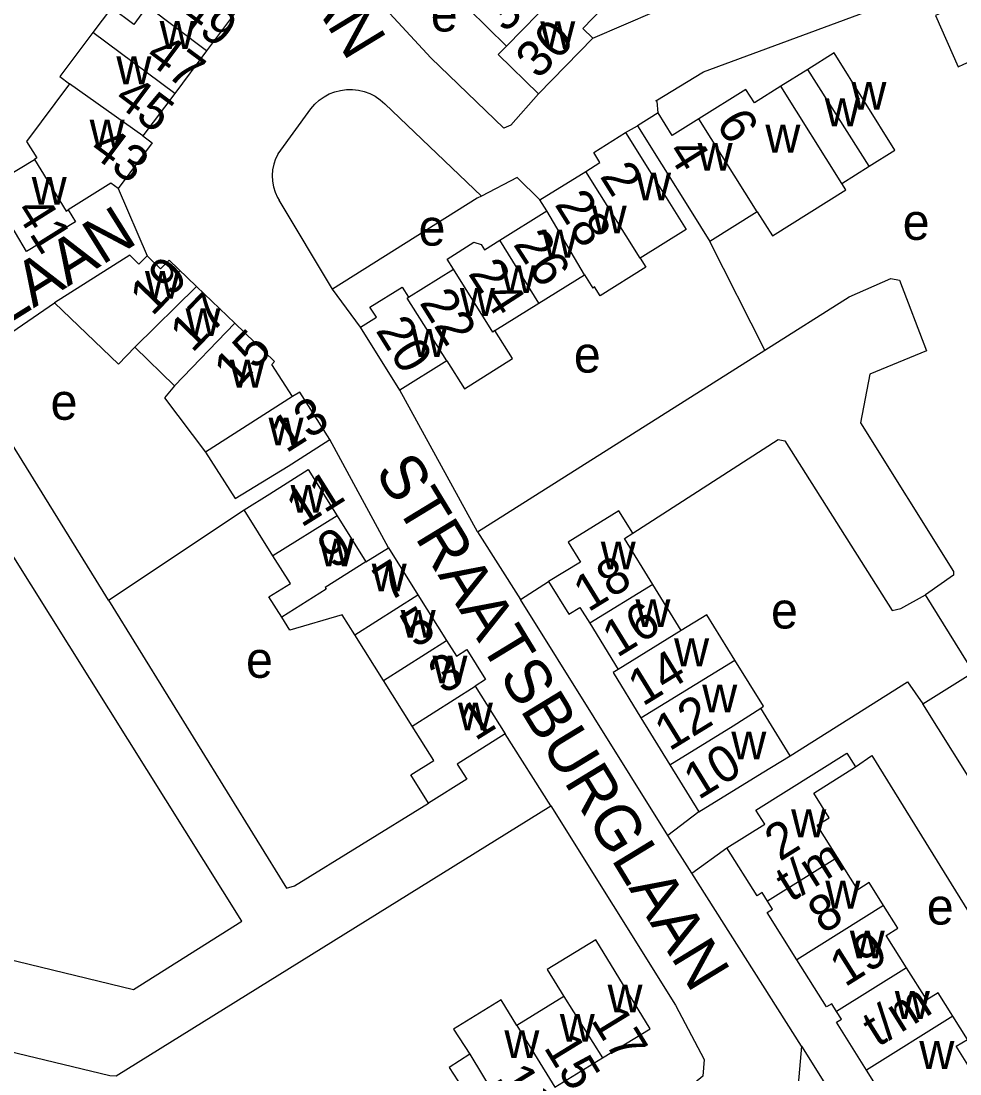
# Model space of a CAD drawing. Extents: x 157768 to 159790, y 387230 to 389604.
# Drawn here: x 158696.4 to 158800.1, y 388182.9 to 388299.1 of the extents above; entities that cross this region are included whole.
import ezdxf

# ---------------------------------------------------------------- set-up
doc = ezdxf.new("R2010")
doc.units = 0
for name, color, linetype in [('BLT_Basislijn', 7, 'Continuous'), ('BLT_Bebouwing', 7, 'Continuous'), ('BLT_Centroide', 7, 'Continuous'), ('BLT_Huisnummer', 7, 'Continuous'), ('BLT_Huisnummer_ tussenligend', 7, 'Continuous'), ('BLT_Huisnummer_reeks', 7, 'Continuous'), ('BLT_Onderverdeling_panden', 7, 'Continuous'), ('BLT_Straatnaam', 7, 'Continuous')]:
    doc.layers.add(name, color=color, linetype=linetype)

msp = doc.modelspace()

# ---------------------------------------------------------------- linework, layer by layer
at = {"layer": 'BLT_Basislijn'}
for p, q in [((158759.54, 388297.26), (158769.82, 388301.71)), ((158724.78, 388284.49), (158728.4, 388289.46)), ((158736.58, 388289.99), (158747.25, 388279.82)), ((158763.16, 388286.83), (158764.46, 388287.58)), ((158707.13, 388280.65), (158710.32, 388273.23)), ((158730.79, 388269.53), (158724.9, 388279.35)), ((158746.78, 388279.58), (158730.79, 388269.53)), ((158747.25, 388279.82), (158746.78, 388279.58)), ((158778.52, 388262.81), (158772.45, 388274.78)), ((158733.87, 388265.33), (158730.79, 388269.53)), ((158746.79, 388242.74), (158778.52, 388262.81)), ((158746.79, 388242.74), (158738.23, 388258.37)), ((158736.96, 388240.97), (158730.51, 388252.94)), ((158706.07, 388235.18), (158721.03, 388245.16)), ((158746.79, 388242.74), (158751.54, 388235.25)), ((158751.54, 388235.25), (158754.66, 388237.24)), ((158767.82, 388209.21), (158751.54, 388235.25)), ((158801.57, 388227.22), (158796.28, 388235.78)), ((158754.91, 388212.48), (158749.86, 388220.41)), ((158771.24, 388211.81), (158767.82, 388209.21)), ((158770.46, 388205.05), (158767.82, 388209.21)), ((158770.46, 388205.05), (158774.34, 388207.84)), ((158782.57, 388185.91), (158770.46, 388205.05)), ((158782.57, 388185.91), (158794.71, 388166.77))]:
    msp.add_line(p, q, dxfattribs=at)
for points in [[(158753.53, 388291.11), (158750.47, 388287.65), (158749.71, 388287.32), (158741.65, 388295.09), (158737.13, 388299.97), (158739.46, 388302.38)], [(158766.75, 388289.01), (158766.65, 388290.26), (158766.48, 388290.33), (158771.75, 388293.55), (158796.8, 388302.82)], [(158728.4, 388289.46), (158728.84, 388289.96), (158729.32, 388290.4), (158729.86, 388290.78), (158730.44, 388291.09), (158731.05, 388291.33), (158731.69, 388291.49), (158732.35, 388291.58), (158733, 388291.59), (158733.66, 388291.51), (158734.3, 388291.36), (158734.92, 388291.13), (158735.5, 388290.83), (158736.05, 388290.46), (158736.58, 388289.99)], [(158724.78, 388284.49), (158724.51, 388283.93), (158724.3, 388283.33), (158724.17, 388282.71), (158724.12, 388282.08), (158724.15, 388281.45), (158724.26, 388280.83), (158724.45, 388280.23), (158724.71, 388279.66), (158724.9, 388279.35)], [(158753.7, 388279.4), (158751.18, 388281.86), (158747.25, 388279.82)], [(158778.52, 388262.81), (158787.84, 388268.69), (158792.44, 388270.72), (158793.4, 388270.53), (158796.38, 388262.74), (158790.14, 388260.15), (158789.09, 388254.78), (158799.37, 388238.34), (158799.37, 388237.95), (158796.28, 388235.78)], [(158706.07, 388235.18), (158705.48, 388236.13), (158693.99, 388254.66), (158690.52, 388260.86), (158690.65, 388261.55), (158700.1, 388268.01)], [(158666.08, 388241.43), (158650.47, 388231.51), (158669.07, 388201.82), (158708.81, 388192.17), (158720.79, 388199.72), (158684.89, 388256.97)], [(158763.95, 388242.59), (158779.99, 388252.92), (158780.72, 388252.8), (158792.6, 388234.05), (158793.55, 388234.28), (158796.28, 388235.78)], [(158706.07, 388235.18), (158725.7, 388203.39), (158726.59, 388203.62), (158741.41, 388212.75)], [(158781.31, 388218.01), (158794.29, 388226.18), (158795.99, 388223.74)], [(158754.91, 388212.48), (158768.65, 388190.46), (158771.84, 388184.46), (158771.68, 388182.61), (158768.32, 388179.87), (158719.99, 388149.59), (158716.6, 388147.54), (158715.16, 388147.58), (158654.55, 388162.64), (158646.18, 388166.5), (158640.59, 388170.73), (158635.71, 388176.23), (158633.8, 388179.81), (158621.93, 388198.67), (158609.83, 388218.76), (158609.61, 388219.13)], [(158788.54, 388216.76), (158790.35, 388218.02), (158814.79, 388178.48)], [(158664.28, 388192.84), (158665.72, 388193.71), (158692.01, 388187.29), (158692.87, 388185.9), (158706.22, 388182.68), (158706.92, 388182.64), (158754.91, 388212.48)], [(158782.57, 388185.91), (158781.74, 388176.16), (158788.72, 388165.04), (158789.73, 388164.14), (158790.36, 388164.14), (158794.71, 388166.77)]]:
    msp.add_lwpolyline(points, dxfattribs=at)
at = {"layer": 'BLT_Bebouwing'}
for p, q in [((158720.41, 388300.58), (158716.89, 388295.87)), ((158749.99, 388296.38), (158745.8, 388300.48)), ((158759.54, 388297.26), (158753.53, 388291.11)), ((158716.89, 388295.87), (158713.37, 388291.16)), ((158713.37, 388291.16), (158709.85, 388286.45)), ((158766.75, 388289.01), (158764.46, 388287.58)), ((158753.7, 388279.4), (158758.78, 388282.54)), ((158787.02, 388281.22), (158790.05, 388283.11)), ((158754.45, 388278.19), (158753.7, 388279.4)), ((158749.28, 388274.95), (158754.45, 388278.19)), ((158777.7, 388278.07), (158772.45, 388274.78)), ((158739.18, 388268.64), (158744.15, 388271.74)), ((158738.23, 388258.37), (158733.87, 388265.33)), ((158708.97, 388263.11), (158713.33, 388258.87)), ((158743.41, 388261.61), (158738.23, 388258.37)), ((158724.22, 388240.07), (158721.03, 388245.16)), ((158731.29, 388244.5), (158734.49, 388239.41)), ((158734.49, 388239.41), (158736.96, 388240.97)), ((158736.96, 388240.97), (158740.22, 388235.78)), ((158740.22, 388235.78), (158743.38, 388230.74)), ((158759.19, 388232.63), (158762.33, 388227.54)), ((158736.43, 388226.31), (158733.27, 388231.35)), ((158795.99, 388223.74), (158801.57, 388227.22)), ((158739.6, 388221.27), (158736.43, 388226.31)), ((158746.55, 388225.7), (158749.86, 388220.41)), ((158803.98, 388210.94), (158795.99, 388223.74)), ((158764.85, 388222.19), (158768.05, 388217)), ((158768.05, 388217), (158771.24, 388211.81)), ((158771.24, 388211.81), (158778.25, 388216.12)), ((158756.34, 388191.4), (158751.16, 388188.22)), ((158755.35, 388181.4), (158760.62, 388184.63))]:
    msp.add_line(p, q, dxfattribs=at)
for points in [[(158759.54, 388297.26), (158758.44, 388298.34), (158760.64, 388300.59), (158757.43, 388303.74), (158755.88, 388302.16), (158755.77, 388302.27)], [(158796.8, 388302.82), (158798.02, 388300.06), (158797.38, 388299.77), (158799.88, 388294.1), (158800.52, 388294.39), (158801.87, 388294.98), (158801.96, 388294.75)], [(158710.34, 388300.77), (158708.85, 388298.78), (158706.39, 388300.62), (158704.34, 388297.87)], [(158704.34, 388297.87), (158700.7, 388293.01), (158701.75, 388292.22)], [(158753.53, 388291.11), (158749.09, 388295.45), (158749.99, 388296.38)], [(158790.05, 388283.11), (158792.9, 388284.9), (158786.19, 388295.62), (158783.29, 388293.81)], [(158783.29, 388293.81), (158780.3, 388291.94)], [(158701.75, 388292.22), (158696.99, 388285.85), (158698.15, 388284.02), (158697.9, 388283.87)], [(158780.3, 388291.94), (158777.38, 388290.11)], [(158777.38, 388290.11), (158776.45, 388291.6), (158771.26, 388288.36)], [(158771.26, 388288.36), (158768.31, 388286.51), (158766.75, 388289.01)], [(158764.46, 388287.58), (158767.12, 388283.34), (158770.4, 388278.1), (158772.45, 388274.78)], [(158709.85, 388286.45), (158710.89, 388285.68), (158707.13, 388280.65)], [(158758.78, 388282.54), (158760.32, 388283.51), (158759.63, 388284.62), (158763.16, 388286.83)], [(158763.16, 388286.83), (158765.81, 388282.59), (158769.86, 388276.13), (158764.78, 388272.96)], [(158695.78, 388275.75), (158694.43, 388277.98), (158692.75, 388280.75), (158697.9, 388283.87)], [(158707.13, 388280.65), (158706.32, 388281.25), (158701.61, 388278.29)], [(158777.7, 388278.07), (158779.36, 388275.42), (158787.47, 388280.49), (158787.02, 388281.22)], [(158701.61, 388278.29), (158702.41, 388276.97), (158697.02, 388273.7), (158695.78, 388275.75)], [(158744.15, 388271.74), (158743.45, 388272.86), (158746.41, 388274.72), (158747.19, 388274.48), (158747.58, 388273.89), (158749.28, 388274.95)], [(158710.32, 388273.23), (158709.42, 388272.29), (158708.43, 388273.29), (158700.1, 388268.01)], [(158715.77, 388269.83), (158712.76, 388272.75), (158711.81, 388271.78), (158710.32, 388273.23)], [(158764.78, 388272.96), (158765.4, 388271.97), (158760.34, 388268.8), (158759.72, 388269.79), (158759.52, 388269.66)], [(158753.59, 388267.98), (158758.6, 388271.12)], [(158758.6, 388271.12), (158759.52, 388269.66)], [(158715.77, 388269.83), (158720.02, 388265.76)], [(158733.87, 388265.33), (158735.64, 388266.43), (158734.93, 388267.56), (158738.47, 388269.77), (158739.18, 388268.64)], [(158700.1, 388268.01), (158707.16, 388261.24), (158708.97, 388263.11)], [(158748.73, 388264.95), (158753.59, 388267.98)], [(158726.37, 388257.67), (158724.08, 388261.22), (158724.4, 388261.54), (158720.02, 388265.76)], [(158743.41, 388261.61), (158745.35, 388258.52), (158750.68, 388261.86), (158748.73, 388264.95)], [(158713.33, 388258.87), (158712.25, 388257.54), (158716.77, 388251.53)], [(158730.51, 388252.94), (158727.17, 388258.17), (158726.37, 388257.67)], [(158716.77, 388251.53), (158720.04, 388246.41), (158725.88, 388250), (158726.29, 388250.26), (158730.51, 388252.94)], [(158721.03, 388245.16), (158723.87, 388246.94), (158728.1, 388249.6), (158731.29, 388244.5)], [(158763.95, 388242.59), (158762.42, 388245.06), (158756.8, 388241.6), (158758.16, 388239.39), (158754.66, 388237.24)], [(158766.15, 388236.92), (158763.02, 388242.01), (158763.95, 388242.59)], [(158725.19, 388233.3), (158723.78, 388235.55), (158726.14, 388237.02), (158724.22, 388240.07)], [(158754.66, 388237.24), (158756.88, 388233.64), (158758.11, 388234.39), (158759.19, 388232.63)], [(158769.29, 388231.83), (158766.15, 388236.92)], [(158733.27, 388231.35), (158731.87, 388233.57), (158726.09, 388231.86), (158725.19, 388233.3)], [(158775.23, 388228.56), (158772.14, 388233.58), (158769.29, 388231.83)], [(158743.38, 388230.74), (158744.47, 388229), (158745.62, 388229.73), (158747.7, 388226.42), (158746.55, 388225.7)], [(158778.07, 388223.27), (158778.38, 388223.46), (158775.23, 388228.56)], [(158762.33, 388227.54), (158761.77, 388227.2), (158764.85, 388222.19)], [(158781.31, 388218.01), (158778.07, 388223.27)], [(158741.41, 388212.75), (158739.43, 388215.91), (158741.97, 388217.49), (158739.6, 388221.27)], [(158749.86, 388220.41), (158744.56, 388217.09), (158745.63, 388215.4), (158741.41, 388212.75)], [(158774.34, 388207.84), (158778.52, 388210.46), (158777.55, 388212.01), (158787.59, 388218.28), (158788.54, 388216.76)], [(158778.25, 388216.12), (158781.31, 388218.01)], [(158786.56, 388206.78), (158784.32, 388210.35), (158785.62, 388211.16), (158783.93, 388213.88), (158788.54, 388216.76)], [(158778.84, 388201.93), (158778.24, 388202.89), (158777.67, 388202.53), (158774.34, 388207.84)], [(158791.64, 388201.47), (158790.06, 388203.99), (158788.8, 388203.21), (158786.56, 388206.78)], [(158782.06, 388195.47), (158778.79, 388200.68), (158779.39, 388201.06), (158778.84, 388201.93)], [(158794.17, 388194.59), (158791.94, 388198.15), (158793.22, 388198.95), (158791.64, 388201.47)], [(158760.62, 388184.63), (158765.88, 388187.86), (158759.87, 388197.66), (158754.51, 388194.38), (158756.34, 388191.4)], [(158786.46, 388189.76), (158785.92, 388190.62), (158785.33, 388190.26), (158782.06, 388195.47)], [(158799.28, 388189.25), (158797.67, 388191.82), (158796.4, 388191.03), (158794.17, 388194.59)], [(158751.16, 388188.22), (158749.43, 388191.04), (158744.17, 388187.8), (158745.96, 388185.03)], [(158789.75, 388183.28), (158786.44, 388188.56), (158786.99, 388188.9), (158786.46, 388189.76)], [(158801.87, 388182.41), (158799.67, 388185.91), (158800.89, 388186.68), (158799.28, 388189.25)], [(158745.96, 388185.03), (158743.68, 388183.56), (158745.1, 388181.37), (158742.12, 388179.52)], [(158794.15, 388177.57), (158793.55, 388178.52), (158792.96, 388178.16), (158789.75, 388183.28)]]:
    msp.add_lwpolyline(points, dxfattribs=at)
at = {"layer": 'BLT_Onderverdeling_panden'}
for p, q in [((158749.99, 388296.38), (158755.77, 388302.27)), ((158716.89, 388295.87), (158710.34, 388300.77)), ((158713.37, 388291.16), (158704.34, 388297.87)), ((158790.05, 388283.11), (158783.29, 388293.81)), ((158709.85, 388286.45), (158701.75, 388292.22)), ((158787.02, 388281.22), (158780.3, 388291.94)), ((158777.7, 388278.07), (158771.26, 388288.36)), ((158764.78, 388272.96), (158758.78, 388282.54)), ((158758.6, 388271.12), (158754.45, 388278.19)), ((158753.59, 388267.98), (158749.28, 388274.95)), ((158715.77, 388269.83), (158708.97, 388263.11)), ((158726.37, 388257.67), (158716.77, 388251.53)), ((158731.29, 388244.5), (158724.22, 388240.07)), ((158766.15, 388236.92), (158759.19, 388232.63)), ((158733.27, 388231.35), (158740.22, 388235.78)), ((158769.29, 388231.83), (158762.33, 388227.54)), ((158736.43, 388226.31), (158743.38, 388230.74)), ((158764.85, 388222.19), (158775.23, 388228.56)), ((158739.6, 388221.27), (158746.55, 388225.7)), ((158775.05, 388221.31), (158778.07, 388223.27)), ((158768.05, 388217), (158775.05, 388221.31)), ((158786.56, 388206.78), (158778.84, 388201.93)), ((158791.64, 388201.47), (158782.06, 388195.47)), ((158794.17, 388194.59), (158786.46, 388189.76)), ((158756.34, 388191.4), (158760.62, 388184.63)), ((158799.28, 388189.25), (158789.75, 388183.28)), ((158751.16, 388188.22), (158755.35, 388181.4)), ((158745.96, 388185.03), (158751.96, 388175.17))]:
    msp.add_line(p, q, dxfattribs=at)
for points in [[(158697.9, 388283.87), (158701.37, 388278.14), (158701.61, 388278.29)], [(158748.73, 388264.95), (158748.5, 388264.8), (158744.15, 388271.74)], [(158743.41, 388261.61), (158739.04, 388268.55), (158739.18, 388268.64)], [(158720.02, 388265.76), (158713.33, 388258.87)], [(158734.49, 388239.41), (158729.98, 388236.59), (158730.1, 388236.39), (158725.19, 388233.3)]]:
    msp.add_lwpolyline(points, dxfattribs=at)

# ---------------------------------------------------------------- texts
at = {"layer": 'BLT_Centroide'}
for s, p in [('e', (158741.64, 388297.99)), ('w', (158711.71, 388296.06)), ('w', (158753.73, 388296.05)), ('w', (158706.93, 388292.16)), ('w', (158788.09, 388289.34)), ('w', (158785.16, 388287.52)), ('w', (158703.97, 388285.19)), ('w', (158778.59, 388284.62)), ('w', (158771.11, 388282.61)), ('w', (158697.58, 388278.86)), ('w', (158764.31, 388279.33)), ('w', (158759.41, 388275.69)), ('e', (158793.75, 388274.98)), ('e', (158740.29, 388274.34)), ('w', (158753.94, 388273.03)), ('w', (158749.38, 388269.11)), ('w', (158710.08, 388268.47)), ('w', (158744.86, 388266.58)), ('w', (158714.56, 388264.36)), ('w', (158739.52, 388262.05)), ('e', (158757.44, 388260.32)), ('w', (158719.45, 388258.66)), ('e', (158699.66, 388255.11)), ('w', (158723.73, 388252.28)), ('w', (158726.16, 388244.84)), ('w', (158729.31, 388238.91)), ('w', (158760.41, 388238.59)), ('w', (158735.12, 388236.16)), ('w', (158764.24, 388232.22)), ('e', (158779.21, 388232.06)), ('w', (158738.32, 388231.03)), ('w', (158768.51, 388227.88)), ('e', (158721.24, 388226.61)), ('w', (158741.83, 388226)), ('w', (158771.62, 388222.78)), ('w', (158744.64, 388220.81)), ('w', (158774.83, 388217.59)), ('w', (158781.44, 388209)), ('w', (158785.21, 388201.12)), ('e', (158796.41, 388199.36)), ('w', (158787.91, 388195.62)), ('w', (158761.16, 388189.66)), ('w', (158792.88, 388188.94)), ('w', (158755.89, 388186.42)), ('w', (158749.77, 388184.61)), ('w', (158795.59, 388183.41))]:
    msp.add_text(s, height=4, dxfattribs=at).set_placement(p)
at = {"layer": 'BLT_Huisnummer'}
for s, rotation, p in [('30', 45.6213, (158753.51, 388292.61)), ('45', 323.2266, (158706.52, 388290.19)), ('6', 302.0416, (158773.07, 388287.84)), ('4', 302.0429, (158767.63, 388284.71)), ('2', 302.0429, (158760.25, 388282.01)), ('41', 302.0977, (158695.66, 388278.19)), ('19', 45.8144, (158710.89, 388266.45)), ('24', 302.8421, (158745.7, 388271.27)), ('20', 302.0446, (158735.49, 388264.97)), ('13', 32.3613, (158725.67, 388251.35)), ('11', 32.0884, (158727.36, 388243.15)), ('18', 31.6171, (158759.03, 388233.8)), ('5', 32.0802, (158739.95, 388229.81)), ('14', 31.6171, (158765.05, 388223.4)), ('1', 32.0802, (158746.55, 388219.58)), ('10', 31.6171, (158771.2, 388213.07)), ('17', 301.5397, (158759.27, 388188.81)), ('13', 301.5397, (158748.81, 388182.44))]:
    msp.add_text(s, height=4, rotation=rotation, dxfattribs=at).set_placement(p)
at = {"layer": 'BLT_Huisnummer_ tussenligend'}
for s, rotation, p in [('32', 45.6213, (158749.9, 388297.73)), ('49', 323.2266, (158713.5, 388299.6)), ('47', 323.2266, (158709.94, 388294.9)), ('43', 323.2266, (158703.77, 388284.61)), ('28', 302.0443, (158755.25, 388278.9)), ('26', 302.8421, (158750.67, 388274.5)), ('17', 45.8144, (158715.32, 388262.41)), ('22', 302.0446, (158740.33, 388268.04)), ('15', 45.8144, (158720.16, 388258.39)), ('9', 32.0802, (158730.81, 388238.54)), ('7', 32.0802, (158736.98, 388234.91)), ('16', 31.6171, (158762.22, 388228.78)), ('3', 32.0802, (158743.07, 388224.71)), ('12', 31.6171, (158767.99, 388218.45)), ('15', 301.5397, (158754.05, 388185.8))]:
    msp.add_text(s, height=4, rotation=rotation, dxfattribs=at).set_placement(p)
at = {"layer": 'BLT_Huisnummer_reeks'}
for s, rotation, p in [('2', 32.0192, (158780.18, 388206.27)), ('t/m', 32.0192, (158781.38, 388201.77)), ('8', 32.0758, (158784.96, 388198.24)), ('19', 32.0888, (158787.37, 388192.39)), ('t/m', 32.0192, (158790.97, 388185.76))]:
    msp.add_text(s, height=4, rotation=rotation, dxfattribs=at).set_placement(p)
at = {"layer": 'BLT_Straatnaam'}
for height, rotation, p in [(4.9999, 301.3651, (158697.43, 388352.32)), (5, 32.026, (158652.1, 388238.84)), (4.9999, 301.3651, (158735.4, 388249.4))]:
    msp.add_text('STRAATSBURGLAAN', height=height, rotation=rotation, dxfattribs=at).set_placement(p)

doc.saveas('drawing.dxf')
